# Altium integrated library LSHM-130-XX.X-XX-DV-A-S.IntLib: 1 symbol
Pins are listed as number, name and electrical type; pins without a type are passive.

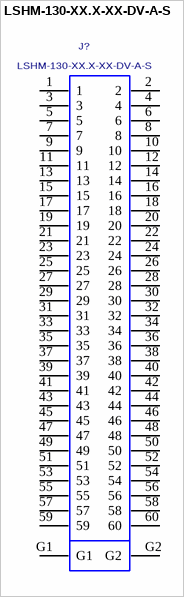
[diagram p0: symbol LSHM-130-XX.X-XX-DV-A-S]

## LSHM-130-XX.X-XX-DV-A-S
designator J?
0.50MM TERMINAL/SOCKET COMBO,60PINS.; MANUFACTURER: SAMTEC
footprint LSHM-130-XX.X-XX-DV-A-S
pins: 1, 2, 3, 4, 5, 6, 7, 8, 9, 10, 11, 12, 13, 14, 15, 16, 17, 18, 19, 20, 21, 22, 23, 24, 25, 26, 27, 28, 29, 30, 31, 32, 33, 34, 35, 36, 37, 38, 39, 40, 41, 42, 43, 44, 45, 46, 47, 48, 49, 50, 51, 52, 53, 54, 55, 56, 57, 58, 59, 60, G1, G2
